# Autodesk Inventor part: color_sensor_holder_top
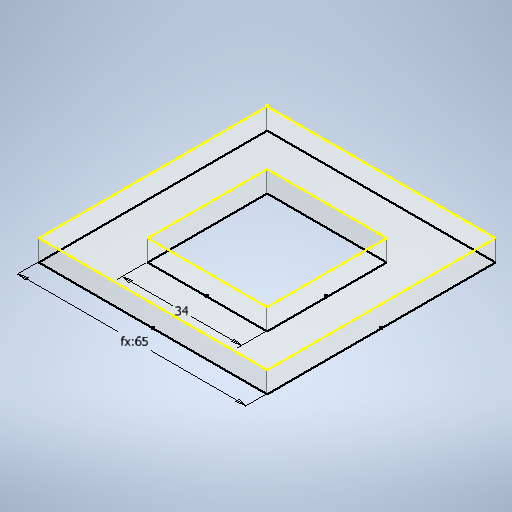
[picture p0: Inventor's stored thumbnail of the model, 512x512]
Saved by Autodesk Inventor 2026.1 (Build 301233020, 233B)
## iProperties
Created: 2026-10
Part Number: color_sensor_holder_top
Material: Generic
Document SubType Name: Modeling
Designer: alolo
Density: 1 g/cm^3
Appearance: Clear
Author: alolo
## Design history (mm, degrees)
sketch "Sketch1"
  geometry: L1 (0, 0)-(-65, 0); L2 (-65, 0)-(-65, 65); L3 (-65, 65)-(0, 65); L4 (0, 65)-(0, 0); L5 (-15.5, 15.5)-(-49.5, 15.5); L6 (-49.5, 15.5)-(-49.5, 49.5); L7 (-49.5, 49.5)-(-15.5, 49.5); L8 (-15.5, 49.5)-(-15.5, 15.5); 4 further points
  constraints: 16 end point, 4 midpoint, 4 parallel, 4 perpendicular, 2 horizontal, 1 horizontal alignment, 1 vertical alignment
  dimensions: "d0" = 65 distance of L2.end L3.end (= slide_width); "d4" = 34 distance of L6.end L7.end
extrude "Extrusion1" new body sketch "Sketch1" distance "d2" = 6 (= aclyric_thickness); taper "d3" = 0 deg
sketch "Sketch2"
  geometry: L1 (0, -65)-(65, -65) reference; L2 (65, -65)-(65, 0) reference; L3 (65, 0)-(0, 0) reference; L4 (0, 0)-(0, -65) reference; L5 (15.5, -15.5)-(49.5, -15.5) reference; L6 (49.5, -15.5)-(49.5, -49.5) reference; L7 (49.5, -49.5)-(15.5, -49.5) reference; L8 (15.5, -49.5)-(15.5, -15.5) reference; 1 further point
  node "Projected Loop1"
body "Solid1"
other parameters: "slide_length" = 195 [user parameter], "slide_angle" = 7 deg [user parameter], "slide_width" = 65 [user parameter; used in 1 equation term], "wood_thickness" = 5 [user parameter], "aclyric_thickness" = 6 [user parameter; used in 1 equation term]
